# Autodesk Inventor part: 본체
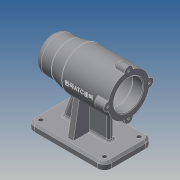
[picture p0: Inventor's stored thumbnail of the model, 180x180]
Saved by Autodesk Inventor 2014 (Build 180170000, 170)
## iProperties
Created: 2019-07
Part Number: 본체
Material: Generic
Document SubType Name: Modeling
Designer: kb542-14
Density: 1 g/cm^3
Appearance: Default
Author: kb542-14
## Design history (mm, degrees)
sketch "스케치1"
  geometry: L1 (59, 0)-(59, 25); L2 (59, 25)-(34, 25); L3 (34, 25)-(14, 30); L4 (14, 30)-(-53, 30); L5 (-53, 30)-(-53, 21); L6 (-53, 21)-(-38, 21); L7 (-38, 21)-(-38, 24); L8 (-38, 24)-(16, 24); L9 (16, 24)-(16, 21); L10 (16, 21)-(28, 21); L11 (28, 21)-(28, 17.5); L12 (28, 17.5)-(46, 17.5); L13 (46, 17.5)-(46, 16); L14 (46, 16)-(50, 16); L15 (50, 16)-(50, 10.5); L16 (50, 10.5)-(53, 10.5); L17 (53, 10.5)-(53, 0); L18 (53, 0)-(59, 0); L19 (53, 0)-(-53, 0); 2 further points
  constraints: 38 end point, 15 parallel, 1 coincident, 1 collinear, 1 midpoint, 1 perpendicular, 1 vertical, 1 vertical alignment
  dimensions: "d0" = 112 distance between parallel lines of L5 L1; "d1" = 45 distance from line of L3.end L1; "d2" = 25 distance of L1.end L2.end; "d3" = 60 diameter of L4 L19; "d4" = 42 diameter of L6 L19; "d5" = 48 diameter of L8 L19; "d6" = 42 diameter of L10 L19; "d7" = 50 diameter of L2 L19; "d8" = 21 diameter of L16 L19; "d9" = 32 diameter of L14 L19; "d10" = 35 diameter of L12 L19; "d11" = 3 distance of L15.end L16.end; "d12" = 4 distance of L13.end L14.end; "d13" = 18 distance of L11.end L12.end; "d14" = 12 distance of L9.end L10.end; "d15" = 54 distance of L7.end L8.end; "d16" = 15 distance of L5.end L6.end
revolve "회전1" sketch "스케치1" stored, may be unused: angle "d17" = 90 deg
sketch "스케치2"
  geometry: A1 r 30 centre (0, 0) between (0, 30) and (-5.97, 29.4) reference; A2 r 6 centre (0, 30) between (5.97, 29.4) and (-5.97, 29.4); 1 further point
  constraints: 5 point on circle, 2 vertical alignment, 1 centre point, 1 other
  dimensions: "d18" = 6 radius of A2
extrude "돌출1" join sketch "스케치2" distance "d19" = 16; taper "d20" = 0 deg
hole "구멍1" diameter "d23" = 3.242; stored, may be unused: countersink angle "d27" = 90 deg, drill point angle "d29" = 118 deg; dims "d21" = 10, "d22" = 10, "d24" = 8, "d25" = 4, "d26" = 2, "d28" = 11
sketch "스케치3"
  geometry: L1 (59, -70)-(-53, -70); L2 (-53, -70)-(-53, -80); L3 (-53, -80)-(59, -80); L4 (59, -80)-(59, -70); L5 (-53, -29.4)-(-53, -36) reference; 2 further points
  constraints: 8 end point, 2 parallel, 1 horizontal, 1 midpoint, 1 perpendicular, 1 vertical alignment
  dimensions: "d33" = 80 distance from line of L3 point (0, 0); "d34" = 10 distance of L1.end L2.end; "d35" = 112 distance of L2.end L3.end
extrude "돌출2" join sketch "스케치3" stored distance "d36" = 70; taper "d37" = 0 deg
node "작업 평면2"
sketch "스케치8"
  geometry: L1 (-10, 70)-(-10, 0) reference; L2 (-57.334, 15.346)-(-10, 7); L3 (-57.334, 54.654)-(-10, 63); L4 (0, 70)-(-10, 70) reference; L5 (-10, 0)-(0, 0) reference; A1 r 30 centre (-80, 35) between (-57.334, 15.346) and (-57.334, 54.654) reference; 1 further point
  constraints: 4 end point, 2 point on circle, 2 point on line
  dimensions: "d82" = 7 distance from line of L4 L3.end; "d83" = 7 distance from line of L5 L2.end; "d84" = 100 deg angle of L2 L1; "d85" = 100 deg angle of L1 L3
extrude "돌출4" join sketch "스케치8" stored distance "d86" = 8; taper "d87" = 0 deg
sketch "스케치5"
  geometry: L1 (14, -30)-(34, -25) reference; L2 (-37, -30)-(14, -30) reference; L3 (59, -70)-(-53, -70) reference; L4 (39, -70)-(23.57, -27.607); L5 (-28, -70)-(-28, -30); L6 (-53, -70)-(-53, -80) reference; L7 (59, -80)-(59, -70) reference; 1 further point
  constraints: 4 end point, 4 point on line, 1 perpendicular
  dimensions: "d44" = 25 distance between parallel lines of L6 L5; "d45" = 20 distance from line of L4.start L7; "d46" = 110 deg angle of L4 L3
feature "리브1" dims "d47" = 1, "d48" = 8, "d49" = 0, "d50" = 0, "d51" = 1, "d52" = 1
feature "리브2" dims "d53" = 1, "d54" = 8, "d55" = 0, "d56" = 0, "d57" = 1, "d58" = 1
fillet "모깎기1" dims "d59" = 10
sketch "스케치6"
  geometry: A1 r 10 centre (0, 60) between (0, 70) and (-10, 60) reference; A2 r 10 centre (0, 10) between (-10, 10) and (0, 0) reference; A3 r 10 centre (92, 10) between (92, 0) and (102, 10) reference; A4 r 10 centre (92, 60) between (102, 60) and (92, 70) reference; 5 further points
  constraints: 4 coincident
hole "구멍2" sketch "스케치6" at (0, 60), (0, 10), (92, 10), (92, 60) diameter "d60" = 6; stored, may be unused: countersink angle "d64" = 90 deg, drill point angle "d66" = 0 deg; dims "d61" = 8, "d62" = 4, "d63" = 2, "d65" = 11
chamfer "모따기1" distance "d67" = 3; stored, may be unused: second distance "d68" = 2, angle "d69" = 45 deg
fillet "모깎기2" dims "d70" = 3, "d71" = 0.3
fillet "모깎기3" dims "d72" = 3, "d73" = 1
chamfer "모따기2" distance "d74" = 1; stored, may be unused: second distance "d75" = 2, angle "d76" = 45 deg
node "작업 평면1"
sketch "스케치7"
  geometry: L1 (53, 30.171)-(53, 36) reference; 2 further points
  constraints: 1 horizontal alignment, 1 other
  dimensions: "d78" = 42 distance from line of point (11, 0) L1
feature "엠보싱1" sketch "스케치7" dims "d0" = 112, "d1" = 45, "d2" = 25, "d3" = 60, "d4" = 42, "d5" = 48, "d6" = 42, "d7" = 50, "d8" = 21, "d9" = 32, "d10" = 35, "d11" = 3, "d12" = 4, "d13" = 18, "d14" = 12, "d15" = 54, "d16" = 15, "d79" = 0.5, "d80" = 0
node "솔리드1"
pattern_circular "원형 패턴1" dims angle "d31" = 360 deg
other parameters: "d81" = -56
